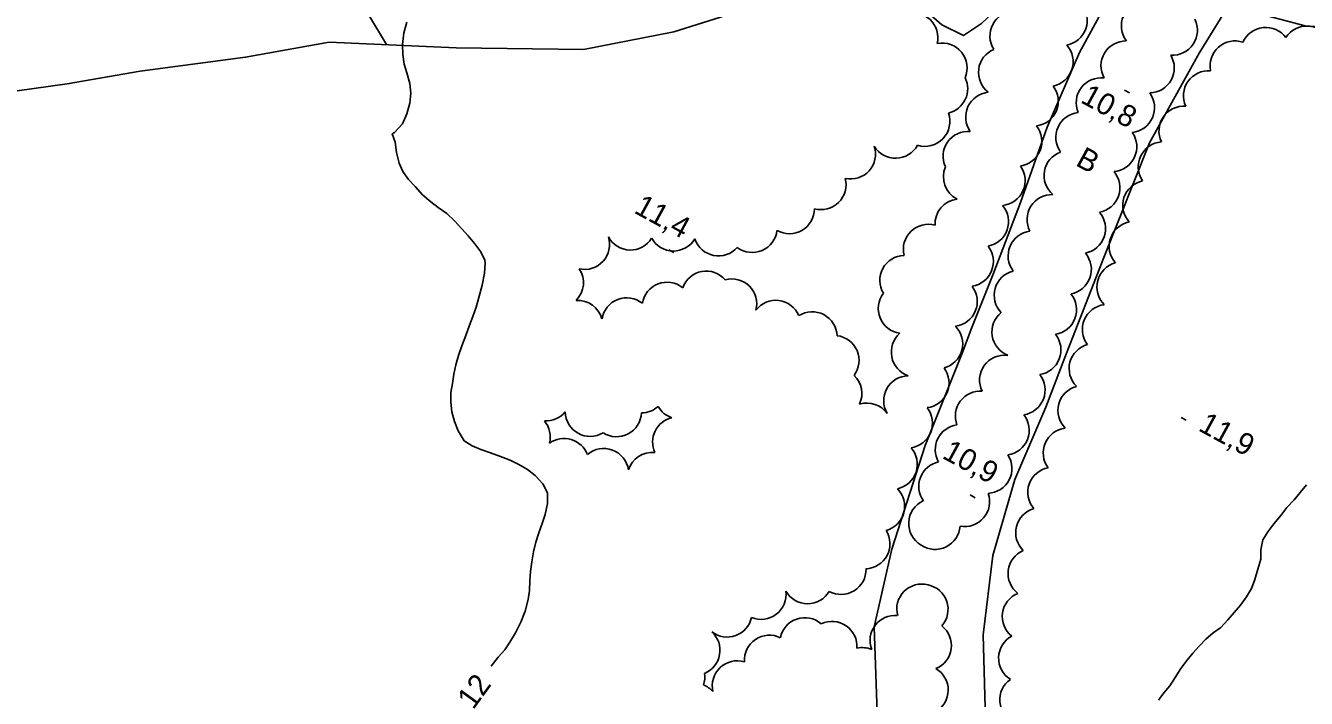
# Model space of a CAD drawing. Extents: x 219136 to 222520, y 5421589 to 5424530.
# Drawn here: x 220010.4 to 220188, y 5423054.4 to 5423147.8 of the extents above; entities that cross this region are included whole.
import ezdxf

# ---------------------------------------------------------------- set-up
doc = ezdxf.new("R2010")
doc.units = 0
for name, color, linetype in [('Level 1', 7, 'Continuous'), ('Level 2', 7, 'Continuous'), ('Level 22', 7, 'Continuous'), ('Level 3', 7, 'Continuous'), ('Level 44', 7, 'Continuous')]:
    doc.layers.add(name, color=color, linetype=linetype)

msp = doc.modelspace()

# ---------------------------------------------------------------- linework, layer by layer
at = {"layer": 'Level 1'}
msp.add_lwpolyline([(220167.5, 5423054.21), (220168.27, 5423055.21), (220169.08, 5423056.19), (220169.83, 5423057.34), (220170.6, 5423058.59), (220171.42, 5423059.68), (220172.28, 5423060.72), (220173.17, 5423061.69), (220174.07, 5423062.65), (220175.07, 5423063.52), (220176.15, 5423064.26), (220177.13, 5423065.36), (220178.01, 5423066.38), (220178.87, 5423067.38), (220179.73, 5423068.53), (220180.41, 5423069.71), (220180.85, 5423070.93), (220181.28, 5423072.39), (220181.71, 5423073.78), (220181.7, 5423075.05), (220181.99, 5423076.46), (220182.68, 5423077.55), (220183.49, 5423078.67), (220184.46, 5423079.83), (220185.33, 5423080.95), (220186.31, 5423082.02), (220187.16, 5423083.02), (220188.06, 5423084.1)], dxfattribs=at)
at = {"layer": 'Level 2'}
for points in [[(220063.25, 5423148.32), (220062.81, 5423146.85), (220062.64, 5423145.19), (220062.71, 5423143.82), (220062.9, 5423142.48), (220063.23, 5423141.27), (220063.68, 5423139.8), (220063.82, 5423138.46), (220063.67, 5423137.07), (220063.24, 5423135.59), (220062.66, 5423134.22), (220061.54, 5423132.99), (220061.22, 5423132.83)], [(220075.91, 5423060.15), (220076.83, 5423061.18), (220077.55, 5423062.25), (220078.32, 5423063.55), (220079.05, 5423065.02), (220079.64, 5423066.56), (220080.06, 5423068.16), (220080.24, 5423069.42), (220080.32, 5423070.74), (220080.41, 5423072.05), (220080.57, 5423073.39), (220080.84, 5423074.76), (220081.14, 5423076.12), (220081.54, 5423077.43), (220082.01, 5423078.71), (220082.42, 5423079.95), (220082.78, 5423081.51), (220082.74, 5423082.97), (220082.12, 5423084.24), (220081.06, 5423085.39), (220079.98, 5423086.19), (220078.79, 5423086.9), (220077.56, 5423087.52), (220076.26, 5423088.03), (220074.87, 5423088.51), (220073.49, 5423088.98), (220072.3, 5423089.51), (220071.19, 5423090.2), (220070.36, 5423091.57), (220069.84, 5423092.86), (220069.51, 5423094.22), (220069.34, 5423095.56), (220069.34, 5423096.92), (220069.59, 5423098.15), (220069.78, 5423099.45), (220070.03, 5423100.76), (220070.41, 5423102.06), (220070.88, 5423103.36), (220071.43, 5423104.83), (220071.96, 5423106.26), (220072.41, 5423107.45), (220072.85, 5423108.76), (220073.24, 5423110.11), (220073.68, 5423111.79), (220074.04, 5423113.45), (220074.13, 5423114.84), (220074.05, 5423115.27), (220073.52, 5423116.42), (220072.68, 5423117.53), (220071.74, 5423118.65), (220070.89, 5423119.62), (220069.88, 5423120.72), (220068.78, 5423121.74), (220067.61, 5423122.6), (220066.56, 5423123.35), (220065.41, 5423124.36), (220064.39, 5423125.49), (220063.5, 5423126.48), (220062.68, 5423127.58), (220062.17, 5423128.73), (220061.8, 5423130.22), (220061.61, 5423131.67), (220061.22, 5423132.83), (220061.22, 5423132.83)], [(220075.91, 5423060.15), (220074.96, 5423058.89)]]:
    msp.add_lwpolyline(points, dxfattribs=at)
at = {"layer": 'Level 22'}
for points in [[(220060.44, 5423145.19), (220044.22, 5423172.24), (220031.1, 5423192.29), (220018.97, 5423207.47), (220008.51, 5423217.42), (219997.78, 5423224.19), (219991.64, 5423230.43), (219984.78, 5423244.27), (219978.44, 5423260.46), (219975.03, 5423276.08), (219973.63, 5423289.41), (219972.86, 5423300.42), (219972.44, 5423301.94)], [(220154.51, 5423101.77), (220159.93, 5423115.62), (220166.24, 5423131.57), (220173.16, 5423143.99), (220181.91, 5423158.23), (220188.95, 5423173.74), (220194.32, 5423187.8), (220199.35, 5423197.42), (220206.67, 5423206.99), (220217.17, 5423220.34), (220225.43, 5423232.91), (220233.79, 5423247.54), (220242.48, 5423263.07), (220251.3, 5423277.34), (220259.8, 5423289.78), (220263.56, 5423295.6), (220266.95, 5423299.42)], [(220002.52, 5423137.86), (220016.12, 5423139.73), (220026.27, 5423141.52), (220040.89, 5423143.45), (220052.47, 5423145.53), (220070.07, 5423144.77), (220087.77, 5423144.52), (220100.29, 5423146.97), (220114.87, 5423151.61), (220125.57, 5423154.61), (220129.08, 5423154.38), (220133.4, 5423151.54), (220137.44, 5423147.94), (220140.44, 5423146.44), (220142.98, 5423148.12), (220147.94, 5423152.85), (220151.94, 5423156.45), (220154.4, 5423158.52), (220157.29, 5423157.75), (220159.43, 5423156.06), (220160.85, 5423155.75), (220163.07, 5423155.93)], [(220160.92, 5423152.11), (220156.56, 5423144.12), (220152.06, 5423133.75), (220148.36, 5423123.26), (220144.56, 5423113.32), (220141.63, 5423105.93), (220140.28, 5423102.37)], [(220204.92, 5423147.49), (220198.19, 5423147.08), (220187.87, 5423147.82), (220182.59, 5423149.19), (220179.8, 5423151.01), (220178.59, 5423152.82)], [(220140.28, 5423102.37), (220135.14, 5423089.56), (220130.5, 5423075.14), (220128.08, 5423064.36), (220128.5, 5423052.47), (220129.2, 5423040.2), (220129.81, 5423029.76), (220131.38, 5423021.95), (220135.56, 5423014.3), (220138.61, 5423008.63)], [(220140.76, 5423007.23), (220143.24, 5423014.45), (220145.18, 5423028.45), (220144.77, 5423042.36), (220143.45, 5423053.14), (220143.21, 5423063.24), (220144.53, 5423074.27), (220147.59, 5423084.82), (220151.88, 5423094.85), (220154.51, 5423101.77)]]:
    msp.add_lwpolyline(points, dxfattribs=at)
at = {"layer": 'Level 3'}
for p, q in [((220162.78, 5423138.87), (220163.48, 5423138.48)), ((220099.6, 5423116.71), (220100.3, 5423116.32)), ((220170.66, 5423093.43), (220171.36, 5423093.04)), ((220141.37, 5423082.69), (220142.08, 5423082.3))]:
    msp.add_line(p, q, dxfattribs=at)
at = {"layer": 'Level 44'}
for centre, start, end in [((220147.59, 5423146.4), 92.4857, 212.4857), ((220154.16, 5423148.54), 280.6157, 40.6157), ((220165.82, 5423147.79), 96.8032, 216.8032), ((220133.46, 5423146.14), 346.8185, 106.8185), ((220169.45, 5423147.19), 266.0899, 26.0899), ((220182.38, 5423144.13), 35.9919, 155.9919), ((220188.11, 5423144.32), 27.7412, 147.7412), ((220137.5, 5423141.95), 337.0261, 101.0971), ((220146, 5423141.34), 112.6216, 232.6216), ((220152.21, 5423142.84), 281.5638, 41.5638), ((220162.99, 5423142.25), 89.0647, 209.0647), ((220178.13, 5423142.25), 71.6524, 191.6524), ((220166.24, 5423141.95), 271.0967, 31.0967), ((220174.43, 5423138.1), 84.9439, 204.9439), ((220137.58, 5423139.07), 283.1412, 26.1946), ((220150.15, 5423137.34), 277.3978, 37.3978), ((220159.55, 5423137.13), 83.1761, 203.1761), ((220144.22, 5423135.14), 95.2453, 215.2453), ((220163.51, 5423136.45), 276.0657, 36.0657), ((220135.11, 5423134.53), 252.6782, 19.8205), ((220156.73, 5423132.32), 95.9454, 215.9454), ((220171.03, 5423133.19), 85.7717, 205.7717), ((220147.87, 5423131.77), 278.1248, 38.1248), ((220141.09, 5423129.69), 85.0792, 205.0792), ((220161.04, 5423131.02), 274.9641, 34.9641), ((220124.79, 5423130), 257.9932, 17.9932), ((220131.04, 5423132.88), 211.3912, 331.3912), ((220155.09, 5423127.03), 109.7482, 229.7482), ((220168.16, 5423128.23), 94.1831, 214.1831), ((220141.13, 5423126.85), 156.7693, 243.238), ((220145.55, 5423126.32), 275.7152, 35.7152), ((220158.7, 5423125.33), 280.2864, 40.2864), ((220120.71, 5423125.75), 254.4517, 14.4517), ((220166.01, 5423122.89), 101.8365, 221.8365), ((220139.98, 5423120.32), 96.7693, 183.238), ((220152.74, 5423120.92), 88.0139, 208.0139), ((220116.32, 5423122.4), 240.1575, 0.1575), ((220143.25, 5423120.63), 280.2617, 40.2617), ((220156.7, 5423119.64), 281.0541, 41.0541), ((220135.58, 5423116.79), 74.1498, 194.1498), ((220164.12, 5423117.19), 101.454, 221.454), ((220087.91, 5423117.45), 257.5975, 17.5975), ((220094.26, 5423120.14), 208.377, 328.377), ((220100.24, 5423120), 208.9207, 328.9207), ((220106.49, 5423119.32), 198.5513, 318.5513), ((220111.15, 5423119.8), 233.3299, 353.3299), ((220150.11, 5423115.86), 97.1625, 217.1625), ((220141.15, 5423115.07), 278.3889, 38.3889), ((220154.74, 5423113.99), 280.586, 40.586), ((220132.31, 5423112.48), 91.4765, 211.4765), ((220162.42, 5423111.55), 105.1001, 225.1001), ((220084.29, 5423112.14), 315.0109, 33.8671), ((220104.78, 5423110.3), 40.5941, 160.5941), ((220108.32, 5423109.21), 345.201, 105.201), ((220148.18, 5423110.4), 103.9315, 223.9315), ((220099.34, 5423108.75), 51.1668, 171.1668), ((220138.91, 5423109.54), 277.3208, 37.3208), ((220086.97, 5423106.23), 15.0109, 93.8671), ((220093.74, 5423106.59), 51.053, 171.053), ((220114.43, 5423106.24), 22.9072, 142.9072), ((220132.1, 5423108.56), 142.2984, 262.2984), ((220152.68, 5423108.4), 279.0777, 39.0777), ((220160.41, 5423105.66), 97.2522, 217.2522), ((220119.47, 5423104.65), 2.2383, 122.2383), ((220147.86, 5423105.3), 128.7786, 248.7786), ((220136.89, 5423103.67), 284.7297, 44.7297), ((220122.52, 5423101.35), 323.148, 83.148), ((220133.91, 5423102.51), 131.0933, 251.0933), ((220150.52, 5423102.82), 278.5661, 38.5661), ((220146.15, 5423098.63), 82.4113, 206.5649), ((220158.57, 5423100.22), 105.2244, 225.2244), ((220135, 5423098.23), 277.077, 37.077), ((220122.91, 5423096.75), 335.287, 46.6834), ((220132.85, 5423095.77), 91.0318, 211.0318), ((220148.32, 5423097.24), 278.447, 38.447), ((220142.79, 5423093.63), 85.6958, 200.7057), ((220157.02, 5423094.41), 104.9698, 224.9698), ((220095.79, 5423097.53), 270.2357, 311.793), ((220101.09, 5423096.69), 210.2357, 251.793), ((220127.05, 5423091.98), 35.287, 106.6834), ((220132.7, 5423092.66), 277.9899, 37.9899), ((220082.55, 5423096.4), 266.7962, 320.4454), ((220079.68, 5423090.74), 345.5586, 39.4956), ((220088.68, 5423094.27), 181.2046, 301.2046), ((220092.34, 5423094.22), 237.4053, 357.4053), ((220100.8, 5423090.03), 103.1392, 204.5897), ((220146.12, 5423091.66), 278.5469, 38.5469), ((220140, 5423088.97), 97.5082, 209.5798), ((220154.98, 5423088.52), 96.8325, 216.8325), ((220085.06, 5423087.06), 20.8918, 125.6277), ((220090.55, 5423085.67), 7.9095, 130.7523), ((220097.3, 5423085.14), 84.2207, 163.1009), ((220130.6, 5423086.93), 281.7199, 41.7199), ((220143.72, 5423086.36), 272.6349, 32.6349), ((220137.71, 5423083.87), 102.0409, 215.5159), ((220152.84, 5423083.04), 100.4807, 220.4807), ((220128.84, 5423081.09), 284.881, 44.881), ((220140.62, 5423081.74), 259.5541, 19.5541), ((220136.32, 5423078.71), 114.4461, 240.022), ((220151.16, 5423077.46), 105.9398, 225.9398), ((220126.8, 5423075.89), 272.2725, 32.2725), ((220136.53, 5423078.58), 235.9671, 355.9671), ((220150.1, 5423071.78), 112.9908, 232.9908), ((220123.48, 5423072.33), 241.5824, 1.5824), ((220134.67, 5423066.85), 75.4442, 195.4442), ((220134.86, 5423066.8), 318.6335, 78.6335), ((220112.4, 5423068.87), 247.3751, 7.3751), ((220118.84, 5423071.03), 209.7403, 329.7403), ((220149.3, 5423065.8), 111.7493, 231.7493), ((220107.68, 5423066.41), 232.3195, 347.6558), ((220118.45, 5423062.18), 48.7828, 168.7828), ((220122.22, 5423061.66), 355.4686, 115.4686), ((220130.96, 5423062.48), 84.6479, 201.0829), ((220135.33, 5423061.78), 292.1385, 52.1385), ((220103.23, 5423061.11), 292.3195, 47.6558), ((220113.53, 5423059.75), 63.9265, 183.9265), ((220148.79, 5423060.03), 118.1747, 238.1747), ((220126.4, 5423058.03), 67.375, 101.9039), ((220109.08, 5423056.19), 73.4118, 193.4118), ((220101.12, 5423057.41), 341.5086, 8.2863), ((220134.88, 5423055.59), 299.5135, 59.5135), ((220103.12, 5423053.09), 41.5086, 68.2863), ((220148.95, 5423054.24), 124.9409, 244.9409)]:
    msp.add_arc(centre, 3.46, start, end, dxfattribs=at)

# ---------------------------------------------------------------- texts
at = {"layer": 'Level 2'}
msp.add_text('12', height=3, rotation=54.0581, dxfattribs=at).set_placement((220072.46, 5423052.77))
at = {"layer": 'Level 3'}
for s, p in [('10,8', (220156.56, 5423137.24)), ('11,4', (220094.61, 5423121.92)), ('11,9', (220172.9, 5423091.69)), ('10,9', (220137.36, 5423087.87))]:
    msp.add_text(s, height=3, rotation=331.383, dxfattribs=at).set_placement(p)
at = {"layer": 'Level 44'}
msp.add_text('B', height=3, rotation=331.3547, dxfattribs=at).set_placement((220155.87, 5423128.5))

doc.saveas('drawing.dxf')
